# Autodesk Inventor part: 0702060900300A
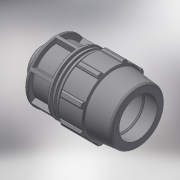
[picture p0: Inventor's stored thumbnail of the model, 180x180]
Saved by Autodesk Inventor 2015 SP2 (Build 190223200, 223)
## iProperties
Created: 2017-02
Part Number: 0702060900300A
Material: Generic
Description: PLASSON MALE ADAPTOR 90-3"
Document SubType Name: Modeling
Designer: KIM
Mass: 964.158 g
Surface Area: 1468.9 cm^2
Volume: 964.158 cm^3
Density: 1 g/cm^3
Appearance: Default
Author: KIM
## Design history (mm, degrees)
derived "87020.ipt"
feature "Solid1::87020.ipt"
tag "TaggingFeature1"
body "Solid1"
other parameters: "d4" = 33.14286, "d5" = 58, "d7" = 152, "d8" = 114, "d9" = 33.14286, "d11" = 6.62857, "d12" = 121.6, "d13" = 120 deg, "d14" = 117, "d15" = 6 deg, "d16" = 136.8, "d18" = 4.5, "d19" = 35 deg, "d20" = 17.5 deg, "d21" = 141.36, "d23" = 0, "d25" = 360 deg, "d27" = 3.04, "d34" = 7.6, "d36" = 0, "d42" = 69.6, "d43" = 4.56, "d46" = 2.7, "d51" = 232, "d52" = 33, "d53" = 1.8, "d55" = 360 deg, "d57" = 87.884, "d58" = 61.5188, "d59" = 46.4, "d61" = 134.064, "d62" = 2.34857, "d63" = 2.34857, "d66" = 4.69714, "E_" = 152, "H_" = 232, "l_2" = 33, "R_" = 87.884, "d60" = 11.74286
